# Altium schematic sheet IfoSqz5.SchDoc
size C; Engineer: Daniel Sigg; DocumentNumber: 10; SheetNumber: 22; SheetTotal: 33
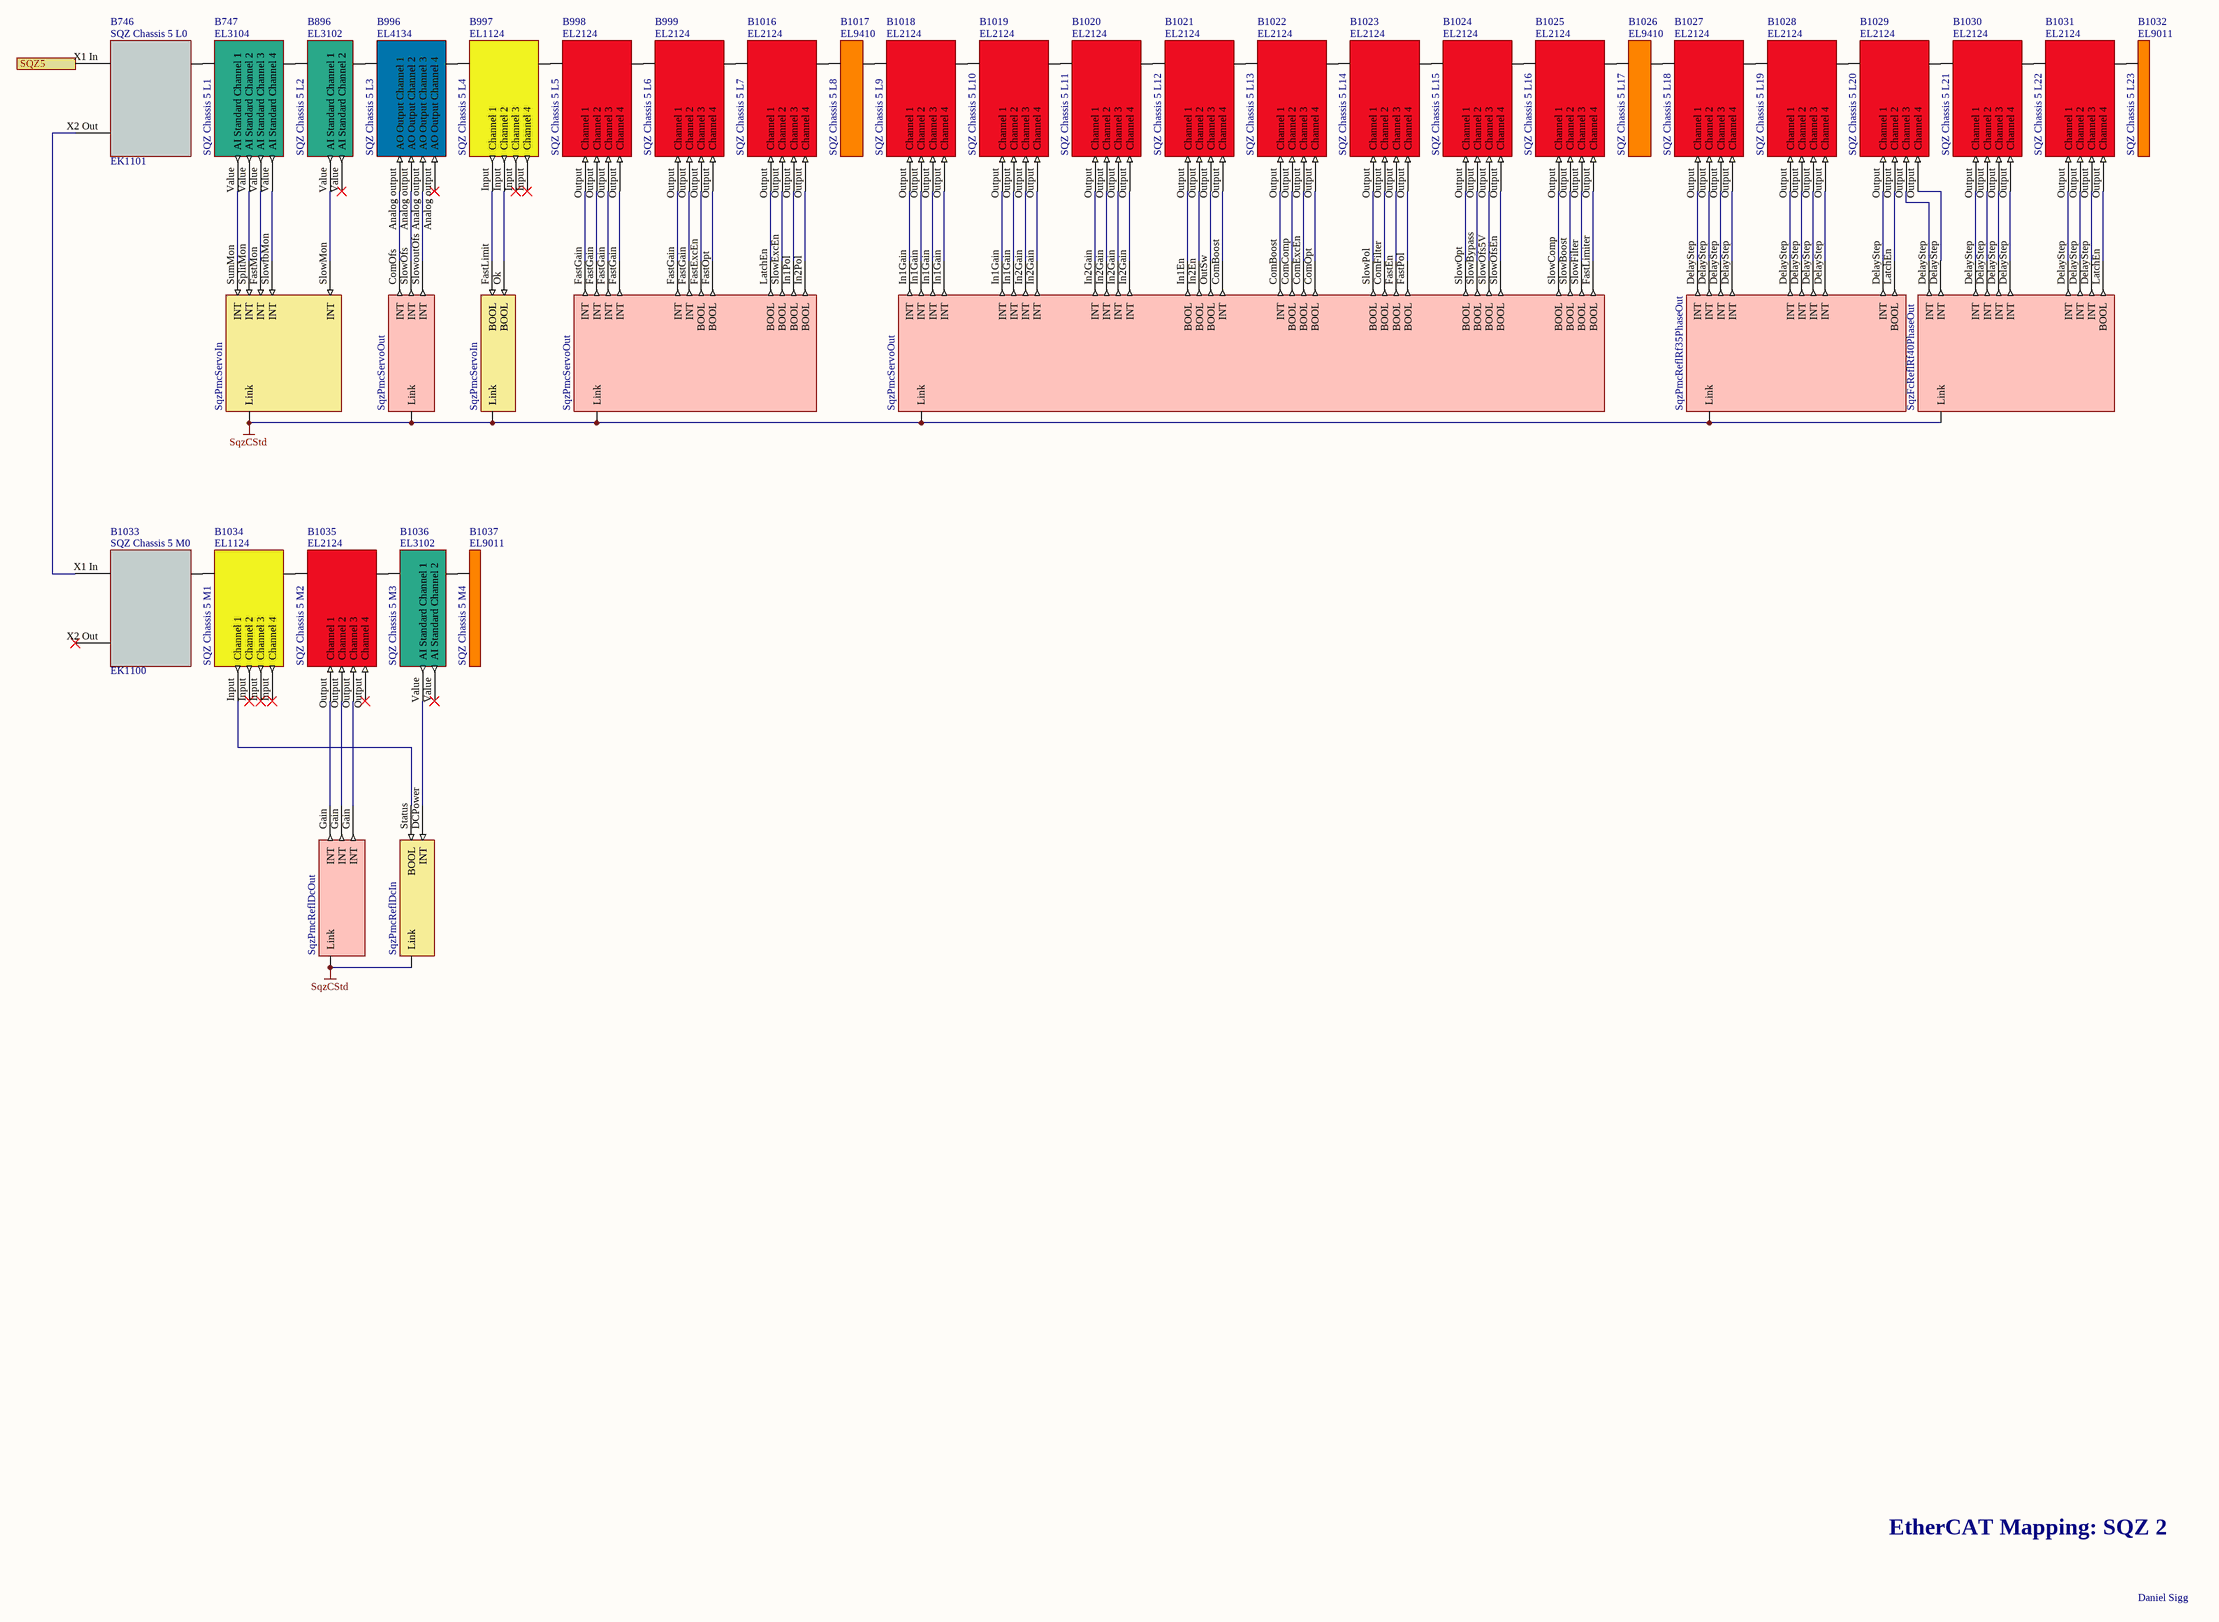
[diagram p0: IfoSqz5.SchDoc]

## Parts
B746  SQZ Chassis 5 L0  Part Number: EK1101
B747  SQZ Chassis 5 L1  Part Number: EL3104  (mechanical)
B896  SQZ Chassis 5 L2  Part Number: EL3102  (mechanical)
B996  SQZ Chassis 5 L3  Part Number: EL4134  (mechanical)
B997  SQZ Chassis 5 L4  Part Number: EL1124  (mechanical)
B998  SQZ Chassis 5 L5  Part Number: EL2124  (mechanical)
B999  SQZ Chassis 5 L6  Part Number: EL2124  (mechanical)
B1016  SQZ Chassis 5 L7  Part Number: EL2124  (mechanical)
B1017  SQZ Chassis 5 L8  Part Number: EL9410  (mechanical)
B1018  SQZ Chassis 5 L9  Part Number: EL2124  (mechanical)
B1019  SQZ Chassis 5 L10  Part Number: EL2124  (mechanical)
B1020  SQZ Chassis 5 L11  Part Number: EL2124  (mechanical)
B1021  SQZ Chassis 5 L12  Part Number: EL2124  (mechanical)
B1022  SQZ Chassis 5 L13  Part Number: EL2124  (mechanical)
B1023  SQZ Chassis 5 L14  Part Number: EL2124  (mechanical)
B1024  SQZ Chassis 5 L15  Part Number: EL2124  (mechanical)
B1025  SQZ Chassis 5 L16  Part Number: EL2124  (mechanical)
B1026  SQZ Chassis 5 L17  Part Number: EL9410  (mechanical)
B1027  SQZ Chassis 5 L18  Part Number: EL2124  (mechanical)
B1028  SQZ Chassis 5 L19  Part Number: EL2124  (mechanical)
B1029  SQZ Chassis 5 L20  Part Number: EL2124  (mechanical)
B1030  SQZ Chassis 5 L21  Part Number: EL2124  (mechanical)
B1031  SQZ Chassis 5 L22  Part Number: EL2124  (mechanical)
B1032  SQZ Chassis 5 L23  Part Number: EL9011  (mechanical)
B1033  SQZ Chassis 5 M0  Part Number: EK1100
B1034  SQZ Chassis 5 M1  Part Number: EL1124  (mechanical)
B1035  SQZ Chassis 5 M2  Part Number: EL2124  (mechanical)
B1036  SQZ Chassis 5 M3  Part Number: EL3102  (mechanical)
B1037  SQZ Chassis 5 M4  Part Number: EL9011  (mechanical)
V868  SqzPmcServoIn  (parts A,B of 2)  (no BOM)
V869  SqzPmcReflRf35PhaseOut  (no BOM)
V870  SqzFcReflRf40PhaseOut  (no BOM)
V871  SqzPmcReflDcOut  (no BOM)
V872  SqzPmcReflDcIn  (no BOM)
V873  SqzPmcServoOut  (parts A,B,C of 3)  (no BOM)

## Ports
SQZ5

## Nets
SqzCStd: V868.0(Link) V868.1(Link) V869.?1(Link) V870.?1(Link) V871.0(Link) V872.1(Link) V873.0(Link) V873.1(Link) V873.2(Link)
SQZ5: B746.X1_In(A) ; port SQZ5
NetB746_Ebus: B746.Ebus(B) B747.Ebus(A)
NetB746_X2 Out: B746.X2_Out(C) B1033.X1_In(A)
NetB747_Ebus: B747.Ebus(B) B896.Ebus(A)
NetB747_Value: B747.Value(AI_Standard_Channel_1) V868.SumMon(INT)
NetB747_Value: B747.Value(AI_Standard_Channel_2) V868.SplitMon(INT)  [a separate net that carries the same name]
NetB747_Value: B747.Value(AI_Standard_Channel_3) V868.FastMon(INT)  [a separate net that carries the same name]
NetB747_Value: B747.Value(AI_Standard_Channel_4) V868.SlowfbMon(INT)  [a separate net that carries the same name]
NetB896_Ebus: B896.Ebus(B) B996.Ebus(A)
NetB896_Value: B896.Value(AI_Standard_Channel_1) V868.SlowMon(INT)
NetB996_Analog output: B996.Analog_output(AO_Output_Channel_1) V873.ComOfs(INT)
NetB996_Analog output: B996.Analog_output(AO_Output_Channel_2) V873.SlowOfs(INT)  [a separate net that carries the same name]
NetB996_Analog output: B996.Analog_output(AO_Output_Channel_3) V873.SlowoutOfs(INT)  [a separate net that carries the same name]
NetB996_Ebus: B996.Ebus(B) B997.Ebus(A)
NetB997_Ebus: B997.Ebus(B) B998.Ebus(A)
NetB997_Input: B997.Input(Channel_1) V868.FastLimit(BOOL)
NetB997_Input: B997.Input(Channel_2) V868.Ok(BOOL)  [a separate net that carries the same name]
NetB998_Ebus: B998.Ebus(B) B999.Ebus(A)
NetB998_Output: B998.Output(Channel_1) V873.FastGain(INT)
NetB998_Output: B998.Output(Channel_2) V873.FastGain(INT)  [a separate net that carries the same name]
NetB998_Output: B998.Output(Channel_3) V873.FastGain(INT)  [a separate net that carries the same name]
NetB998_Output: B998.Output(Channel_4) V873.FastGain(INT)  [a separate net that carries the same name]
NetB999_Ebus: B999.Ebus(B) B1016.Ebus(A)
NetB999_Output: B999.Output(Channel_1) V873.FastGain(INT)
NetB999_Output: B999.Output(Channel_2) V873.FastGain(INT)  [a separate net that carries the same name]
NetB999_Output: B999.Output(Channel_3) V873.FastExcEn(BOOL)  [a separate net that carries the same name]
NetB999_Output: B999.Output(Channel_4) V873.FastOpt(BOOL)  [a separate net that carries the same name]
NetB1016_Ebus: B1016.Ebus(B) B1017.Ebus(A)
NetB1016_Output: B1016.Output(Channel_1) V873.LatchEn(BOOL)
NetB1016_Output: B1016.Output(Channel_2) V873.SlowExcEn(BOOL)  [a separate net that carries the same name]
NetB1016_Output: B1016.Output(Channel_3) V873.In1Pol(BOOL)  [a separate net that carries the same name]
NetB1016_Output: B1016.Output(Channel_4) V873.In2Pol(BOOL)  [a separate net that carries the same name]
NetB1017_Ebus: B1017.Ebus(B) B1018.Ebus(A)
NetB1018_Ebus: B1018.Ebus(B) B1019.Ebus(A)
NetB1018_Output: B1018.Output(Channel_1) V873.In1Gain(INT)
NetB1018_Output: B1018.Output(Channel_2) V873.In1Gain(INT)  [a separate net that carries the same name]
NetB1018_Output: B1018.Output(Channel_3) V873.In1Gain(INT)  [a separate net that carries the same name]
NetB1018_Output: B1018.Output(Channel_4) V873.In1Gain(INT)  [a separate net that carries the same name]
NetB1019_Ebus: B1019.Ebus(B) B1020.Ebus(A)
NetB1019_Output: B1019.Output(Channel_1) V873.In1Gain(INT)
NetB1019_Output: B1019.Output(Channel_2) V873.In1Gain(INT)  [a separate net that carries the same name]
NetB1019_Output: B1019.Output(Channel_3) V873.In2Gain(INT)  [a separate net that carries the same name]
NetB1019_Output: B1019.Output(Channel_4) V873.In2Gain(INT)  [a separate net that carries the same name]
NetB1020_Ebus: B1020.Ebus(B) B1021.Ebus(A)
NetB1020_Output: B1020.Output(Channel_1) V873.In2Gain(INT)
NetB1020_Output: B1020.Output(Channel_2) V873.In2Gain(INT)  [a separate net that carries the same name]
NetB1020_Output: B1020.Output(Channel_3) V873.In2Gain(INT)  [a separate net that carries the same name]
NetB1020_Output: B1020.Output(Channel_4) V873.In2Gain(INT)  [a separate net that carries the same name]
NetB1021_Ebus: B1021.Ebus(B) B1022.Ebus(A)
NetB1021_Output: B1021.Output(Channel_1) V873.In1En(BOOL)
NetB1021_Output: B1021.Output(Channel_2) V873.In2En(BOOL)  [a separate net that carries the same name]
NetB1021_Output: B1021.Output(Channel_3) V873.OutSw(BOOL)  [a separate net that carries the same name]
NetB1021_Output: B1021.Output(Channel_4) V873.ComBoost(INT)  [a separate net that carries the same name]
NetB1022_Ebus: B1022.Ebus(B) B1023.Ebus(A)
NetB1022_Output: B1022.Output(Channel_1) V873.ComBoost(INT)
NetB1022_Output: B1022.Output(Channel_2) V873.ComComp(BOOL)  [a separate net that carries the same name]
NetB1022_Output: B1022.Output(Channel_3) V873.ComExcEn(BOOL)  [a separate net that carries the same name]
NetB1022_Output: B1022.Output(Channel_4) V873.ComOpt(BOOL)  [a separate net that carries the same name]
NetB1023_Ebus: B1023.Ebus(B) B1024.Ebus(A)
NetB1023_Output: B1023.Output(Channel_1) V873.SlowPol(BOOL)
NetB1023_Output: B1023.Output(Channel_2) V873.ComFilter(BOOL)  [a separate net that carries the same name]
NetB1023_Output: B1023.Output(Channel_3) V873.FastEn(BOOL)  [a separate net that carries the same name]
NetB1023_Output: B1023.Output(Channel_4) V873.FastPol(BOOL)  [a separate net that carries the same name]
NetB1024_Ebus: B1024.Ebus(B) B1025.Ebus(A)
NetB1024_Output: B1024.Output(Channel_1) V873.SlowOpt(BOOL)
NetB1024_Output: B1024.Output(Channel_2) V873.SlowBypass(BOOL)  [a separate net that carries the same name]
NetB1024_Output: B1024.Output(Channel_3) V873.SlowOfs5V(BOOL)  [a separate net that carries the same name]
NetB1024_Output: B1024.Output(Channel_4) V873.SlowOfsEn(BOOL)  [a separate net that carries the same name]
NetB1025_Ebus: B1025.Ebus(B) B1026.Ebus(A)
NetB1025_Output: B1025.Output(Channel_1) V873.SlowComp(BOOL)
NetB1025_Output: B1025.Output(Channel_2) V873.SlowBoost(BOOL)  [a separate net that carries the same name]
NetB1025_Output: B1025.Output(Channel_3) V873.SlowFilter(BOOL)  [a separate net that carries the same name]
NetB1025_Output: B1025.Output(Channel_4) V873.FastLimiter(BOOL)  [a separate net that carries the same name]
NetB1026_Ebus: B1026.Ebus(B) B1027.Ebus(A)
NetB1027_Ebus: B1027.Ebus(B) B1028.Ebus(A)
NetB1027_Output: B1027.Output(Channel_1) V869.DelayStep(INT)
NetB1027_Output: B1027.Output(Channel_2) V869.DelayStep(INT)  [a separate net that carries the same name]
NetB1027_Output: B1027.Output(Channel_3) V869.DelayStep(INT)  [a separate net that carries the same name]
NetB1027_Output: B1027.Output(Channel_4) V869.DelayStep(INT)  [a separate net that carries the same name]
NetB1028_Ebus: B1028.Ebus(B) B1029.Ebus(A)
NetB1028_Output: B1028.Output(Channel_1) V869.DelayStep(INT)
NetB1028_Output: B1028.Output(Channel_2) V869.DelayStep(INT)  [a separate net that carries the same name]
NetB1028_Output: B1028.Output(Channel_3) V869.DelayStep(INT)  [a separate net that carries the same name]
NetB1028_Output: B1028.Output(Channel_4) V869.DelayStep(INT)  [a separate net that carries the same name]
NetB1029_Ebus: B1029.Ebus(B) B1030.Ebus(A)
NetB1029_Output: B1029.Output(Channel_1) V869.DelayStep(INT)
NetB1029_Output: B1029.Output(Channel_2) V869.LatchEn(BOOL)  [a separate net that carries the same name]
NetB1029_Output: B1029.Output(Channel_3) V870.DelayStep(INT)  [a separate net that carries the same name]
NetB1029_Output: B1029.Output(Channel_4) V870.DelayStep(INT)  [a separate net that carries the same name]
NetB1030_Ebus: B1030.Ebus(B) B1031.Ebus(A)
NetB1030_Output: B1030.Output(Channel_1) V870.DelayStep(INT)
NetB1030_Output: B1030.Output(Channel_2) V870.DelayStep(INT)  [a separate net that carries the same name]
NetB1030_Output: B1030.Output(Channel_3) V870.DelayStep(INT)  [a separate net that carries the same name]
NetB1030_Output: B1030.Output(Channel_4) V870.DelayStep(INT)  [a separate net that carries the same name]
NetB1031_Ebus: B1031.Ebus(B) B1032.Ebus(A)
NetB1031_Output: B1031.Output(Channel_1) V870.DelayStep(INT)
NetB1031_Output: B1031.Output(Channel_2) V870.DelayStep(INT)  [a separate net that carries the same name]
NetB1031_Output: B1031.Output(Channel_3) V870.DelayStep(INT)  [a separate net that carries the same name]
NetB1031_Output: B1031.Output(Channel_4) V870.LatchEn(BOOL)  [a separate net that carries the same name]
NetB1033_Ebus: B1033.Ebus(B) B1034.Ebus(A)
NetB1034_Ebus: B1034.Ebus(B) B1035.Ebus(A)
NetB1034_Input: B1034.Input(Channel_1) V872.Status(BOOL)
NetB1035_Ebus: B1035.Ebus(B) B1036.Ebus(A)
NetB1035_Output: B1035.Output(Channel_1) V871.Gain(INT)
NetB1035_Output: B1035.Output(Channel_2) V871.Gain(INT)  [a separate net that carries the same name]
NetB1035_Output: B1035.Output(Channel_3) V871.Gain(INT)  [a separate net that carries the same name]
NetB1036_Ebus: B1036.Ebus(B) B1037.Ebus(A)
NetB1036_Value: B1036.Value(AI_Standard_Channel_1) V872.DCPower(INT)

Not connected (* = marked no-connect by the designer): B1033 X2 Out(C)*

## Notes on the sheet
- EtherCAT Mapping: SQZ 2
- Daniel Sigg

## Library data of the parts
B746 = CouplerEK1101: EtherCAT Coupler; Rail: Left; BoxNextB: LKYXOSUU; BoxNextC: LKDMUIJW; BoxPrev: CWDKXLUE; PortPrevFull: 1240/C; PortPrevShort: C 'X2 Out'; Fullname: TIID^Vertex Squeezer (EtherCAT)^SQZ Chassis 5 L0 (EK1101); BoxPorts: Junction; BoxAddr: 1253; Disabled: False
B747 = TerminalEL3104: EtherCAT Terminal EL3104 4-chn Analog Input; Rail: Left; BoxNextB: JVLGVOLS; BoxPrev: JQVLJOFM; PortPrevFull: 1253/B; PortPrevShort: B; Fullname: TIID^Vertex Squeezer (EtherCAT)^SQZ Chassis 5 L0 (EK1101)^SQZ Chassis 5 L1 (EL3104); BoxAddr: 1254; Disabled: False
B896 = TerminalEL3102: EtherCAT Terminal EL3102 2-chn Analog Input; Rail: Left; BoxNextB: BEMJPELD; BoxPrev: LKYXOSUU; PortPrevFull: 1254/B; PortPrevShort: B; Fullname: TIID^Vertex Squeezer (EtherCAT)^SQZ Chassis 5 L0 (EK1101)^SQZ Chassis 5 L2 (EL3102); BoxAddr: 1255; Disabled: False
B996 = TerminalEL4134: EtherCAT Terminal EL4134 4-chn Analog Ouput; Rail: Left; BoxNextB: KFGECLUF; BoxPrev: JVLGVOLS; PortPrevFull: 1255/B; PortPrevShort: B; Fullname: TIID^Vertex Squeezer (EtherCAT)^SQZ Chassis 5 L0 (EK1101)^SQZ Chassis 5 L3 (EL4134); BoxAddr: 1256; Disabled: False
B997 = TerminalEL1124: EtherCAT Terminal EL1124 4-chn Digital Input; Rail: Left; BoxNextB: XXYSQFDN; BoxPrev: BEMJPELD; PortPrevFull: 1256/B; PortPrevShort: B; Fullname: TIID^Vertex Squeezer (EtherCAT)^SQZ Chassis 5 L0 (EK1101)^SQZ Chassis 5 L4 (EL1124); BoxAddr: 1257; Disabled: False
B998 = TerminalEL2124: EtherCAT Terminal EL2124 4-chn Digital Ouput; Rail: Left; BoxNextB: NKADTWFC; BoxPrev: KFGECLUF; PortPrevFull: 1257/B; PortPrevShort: B; Fullname: TIID^Vertex Squeezer (EtherCAT)^SQZ Chassis 5 L0 (EK1101)^SQZ Chassis 5 L5 (EL2124); BoxAddr: 1258; Disabled: False
B999 = TerminalEL2124: EtherCAT Terminal EL2124 4-chn Digital Ouput; Rail: Left; BoxNextB: BBCHXAVO; BoxPrev: XXYSQFDN; PortPrevFull: 1258/B; PortPrevShort: B; Fullname: TIID^Vertex Squeezer (EtherCAT)^SQZ Chassis 5 L0 (EK1101)^SQZ Chassis 5 L6 (EL2124); BoxAddr: 1259; Disabled: False
B1016 = TerminalEL2124: EtherCAT Terminal EL2124 4-chn Digital Ouput; Rail: Left; BoxNextB: KRYXCAPR; BoxPrev: NKADTWFC; PortPrevFull: 1259/B; PortPrevShort: B; Fullname: TIID^Vertex Squeezer (EtherCAT)^SQZ Chassis 5 L0 (EK1101)^SQZ Chassis 5 L7 (EL2124); BoxAddr: 1260; Disabled: False
B1017 = TerminalEL9410: EtherCAT Terminal EL9410 Power; Rail: Left; BoxNextB: IYADOACW; BoxPrev: BBCHXAVO; PortPrevFull: 1260/B; PortPrevShort: B; Fullname: TIID^Vertex Squeezer (EtherCAT)^SQZ Chassis 5 L0 (EK1101)^SQZ Chassis 5 L8 (EL9410); BoxAddr: 1261; Disabled: False
B1018 = TerminalEL2124: EtherCAT Terminal EL2124 4-chn Digital Ouput; Rail: Left; BoxNextB: FWAQFTHP; BoxPrev: KRYXCAPR; PortPrevFull: 1261/B; PortPrevShort: B; Fullname: TIID^Vertex Squeezer (EtherCAT)^SQZ Chassis 5 L0 (EK1101)^SQZ Chassis 5 L9 (EL2124); BoxAddr: 1262; Disabled: False
B1019 = TerminalEL2124: EtherCAT Terminal EL2124 4-chn Digital Ouput; Rail: Left; BoxNextB: YNBMSKFQ; BoxPrev: IYADOACW; PortPrevFull: 1262/B; PortPrevShort: B; Fullname: TIID^Vertex Squeezer (EtherCAT)^SQZ Chassis 5 L0 (EK1101)^SQZ Chassis 5 L10 (EL2124); BoxAddr: 1263; Disabled: False
B1020 = TerminalEL2124: EtherCAT Terminal EL2124 4-chn Digital Ouput; Rail: Left; BoxNextB: RSFOLQSB; BoxPrev: FWAQFTHP; PortPrevFull: 1263/B; PortPrevShort: B; Fullname: TIID^Vertex Squeezer (EtherCAT)^SQZ Chassis 5 L0 (EK1101)^SQZ Chassis 5 L11 (EL2124); BoxAddr: 1264; Disabled: False
B1021 = TerminalEL2124: EtherCAT Terminal EL2124 4-chn Digital Ouput; Rail: Left; BoxNextB: WUOQKASJ; BoxPrev: YNBMSKFQ; PortPrevFull: 1264/B; PortPrevShort: B; Fullname: TIID^Vertex Squeezer (EtherCAT)^SQZ Chassis 5 L0 (EK1101)^SQZ Chassis 5 L12 (EL2124); BoxAddr: 1265; Disabled: False
B1022 = TerminalEL2124: EtherCAT Terminal EL2124 4-chn Digital Ouput; Rail: Left; BoxNextB: RPVQQTWJ; BoxPrev: RSFOLQSB; PortPrevFull: 1265/B; PortPrevShort: B; Fullname: TIID^Vertex Squeezer (EtherCAT)^SQZ Chassis 5 L0 (EK1101)^SQZ Chassis 5 L13 (EL2124); BoxAddr: 1266; Disabled: False
B1023 = TerminalEL2124: EtherCAT Terminal EL2124 4-chn Digital Ouput; Rail: Left; BoxNextB: MLVVBFMT; BoxPrev: WUOQKASJ; PortPrevFull: 1266/B; PortPrevShort: B; Fullname: TIID^Vertex Squeezer (EtherCAT)^SQZ Chassis 5 L0 (EK1101)^SQZ Chassis 5 L14 (EL2124); BoxAddr: 1267; Disabled: False
B1024 = TerminalEL2124: EtherCAT Terminal EL2124 4-chn Digital Ouput; Rail: Left; BoxNextB: SGWXRRPH; BoxPrev: RPVQQTWJ; PortPrevFull: 1267/B; PortPrevShort: B; Fullname: TIID^Vertex Squeezer (EtherCAT)^SQZ Chassis 5 L0 (EK1101)^SQZ Chassis 5 L15 (EL2124); BoxAddr: 1268; Disabled: False
B1025 = TerminalEL2124: EtherCAT Terminal EL2124 4-chn Digital Ouput; Rail: Left; BoxNextB: CTCISQMT; BoxPrev: MLVVBFMT; PortPrevFull: 1268/B; PortPrevShort: B; Fullname: TIID^Vertex Squeezer (EtherCAT)^SQZ Chassis 5 L0 (EK1101)^SQZ Chassis 5 L16 (EL2124); BoxAddr: 1269; Disabled: False
B1026 = TerminalEL9410: EtherCAT Terminal EL9410 Power; Rail: Left; BoxNextB: AVCHSOEV; BoxPrev: SGWXRRPH; PortPrevFull: 1269/B; PortPrevShort: B; Fullname: TIID^Vertex Squeezer (EtherCAT)^SQZ Chassis 5 L0 (EK1101)^SQZ Chassis 5 L17 (EL9410); BoxAddr: 1270; Disabled: False
B1027 = TerminalEL2124: EtherCAT Terminal EL2124 4-chn Digital Ouput; Rail: Left; BoxNextB: RNOAQAFY; BoxPrev: CTCISQMT; PortPrevFull: 1270/B; PortPrevShort: B; Fullname: TIID^Vertex Squeezer (EtherCAT)^SQZ Chassis 5 L0 (EK1101)^SQZ Chassis 5 L18 (EL2124); BoxAddr: 1271; Disabled: False
B1028 = TerminalEL2124: EtherCAT Terminal EL2124 4-chn Digital Ouput; Rail: Left; BoxNextB: MVUKHKFD; BoxPrev: AVCHSOEV; PortPrevFull: 1271/B; PortPrevShort: B; Fullname: TIID^Vertex Squeezer (EtherCAT)^SQZ Chassis 5 L0 (EK1101)^SQZ Chassis 5 L19 (EL2124); BoxAddr: 1272; Disabled: False
B1029 = TerminalEL2124: EtherCAT Terminal EL2124 4-chn Digital Ouput; Rail: Left; BoxNextB: BATIWAGG; BoxPrev: RNOAQAFY; PortPrevFull: 1272/B; PortPrevShort: B; Fullname: TIID^Vertex Squeezer (EtherCAT)^SQZ Chassis 5 L0 (EK1101)^SQZ Chassis 5 L20 (EL2124); BoxAddr: 1273; Disabled: False
B1030 = TerminalEL2124: EtherCAT Terminal EL2124 4-chn Digital Ouput; Rail: Left; BoxNextB: OYHVUHQP; BoxPrev: MVUKHKFD; PortPrevFull: 1273/B; PortPrevShort: B; Fullname: TIID^Vertex Squeezer (EtherCAT)^SQZ Chassis 5 L0 (EK1101)^SQZ Chassis 5 L21 (EL2124); BoxAddr: 1274; Disabled: False
B1031 = TerminalEL2124: EtherCAT Terminal EL2124 4-chn Digital Ouput; Rail: Left; BoxNextB: ODKNBTAG; BoxPrev: BATIWAGG; PortPrevFull: 1274/B; PortPrevShort: B; Fullname: TIID^Vertex Squeezer (EtherCAT)^SQZ Chassis 5 L0 (EK1101)^SQZ Chassis 5 L22 (EL2124); BoxAddr: 1275; Disabled: False
B1032 = TerminalEL9011: EtherCAT Terminal EL9011 End; BoxType: TerminalPassive; Rail: Left; BoxPrev: OYHVUHQP; PortPrevShort: B; Fullname: TIID^Vertex Squeezer (EtherCAT)^SQZ Chassis 5 L0 (EK1101)^SQZ Chassis 5 L23 (EL9011); Disabled: False
B1033 = CouplerEK1100: EtherCAT Coupler; Rail: Middle; BoxNextB: FLDENWVA; BoxPrev: JQVLJOFM; PortPrevFull: 1253/C; PortPrevShort: C 'X2 Out'; Fullname: TIID^Vertex Squeezer (EtherCAT)^SQZ Chassis 5 M0 (EK1100); BoxPorts: Junction; BoxAddr: 1276; Disabled: False
B1034 = TerminalEL1124: EtherCAT Terminal EL1124 4-chn Digital Input; Rail: Middle; BoxNextB: PTDDMXXB; BoxPrev: LKDMUIJW; PortPrevFull: 1276/B; PortPrevShort: B; Fullname: TIID^Vertex Squeezer (EtherCAT)^SQZ Chassis 5 M0 (EK1100)^SQZ Chassis 5 M1 (EL1124); BoxAddr: 1277; Disabled: False
B1035 = TerminalEL2124: EtherCAT Terminal EL2124 4-chn Digital Ouput; Rail: Middle; BoxNextB: PCGSTQTN; BoxPrev: FLDENWVA; PortPrevFull: 1277/B; PortPrevShort: B; Fullname: TIID^Vertex Squeezer (EtherCAT)^SQZ Chassis 5 M0 (EK1100)^SQZ Chassis 5 M2 (EL2124); BoxAddr: 1278; Disabled: False
B1036 = TerminalEL3102: EtherCAT Terminal EL3102 2-chn Analog Input; Rail: Middle; BoxNextB: FMNHAXUQ; BoxPrev: PTDDMXXB; PortPrevFull: 1278/B; PortPrevShort: B; Fullname: TIID^Vertex Squeezer (EtherCAT)^SQZ Chassis 5 M0 (EK1100)^SQZ Chassis 5 M3 (EL3102); BoxAddr: 1279; Disabled: False
B1037 = TerminalEL9011: EtherCAT Terminal EL9011 End; BoxType: TerminalPassive; Rail: Middle; BoxPrev: PCGSTQTN; PortPrevShort: B; Fullname: TIID^Vertex Squeezer (EtherCAT)^SQZ Chassis 5 M0 (EK1100)^SQZ Chassis 5 M4 (EL9011); Disabled: False
V868 = CommonMode_CommonModeInStructB: CommonModeInStruct; BoxType: Variable; Instance: H1SqzCorner Instance; PLC: H1SqzCorner; Task: SqzCStd
V869 = DelayLogic_DelayLogicOutStruct: DelayLogicOutStruct; BoxType: Variable; Instance: H1SqzCorner Instance; PLC: H1SqzCorner; Task: SqzCStd
V870 = DelayLogic_DelayLogicOutStructB: DelayLogicOutStruct; BoxType: Variable; Instance: H1SqzCorner Instance; PLC: H1SqzCorner; Task: SqzCStd
V871 = DCPower_DCPowerOutStructLegacy: DCPowerOutStruct; BoxType: Variable; Instance: H1SqzCorner Instance; PLC: H1SqzCorner; Task: SqzCStd
V872 = DCPower_DCPowerInStructLegacy: DCPowerInStruct; BoxType: Variable; Instance: H1SqzCorner Instance; PLC: H1SqzCorner; Task: SqzCStd
V873 = CommonMode_CommonModeOutStructC: CommonModeOutStruct; BoxType: Variable; Instance: H1SqzCorner Instance; PLC: H1SqzCorner; Task: SqzCStd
